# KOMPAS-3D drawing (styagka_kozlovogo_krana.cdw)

Referenced files: стяжка козлового крана.cdw
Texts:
  СДМ1-12.00.000 СБ
  Стяжка козлового крана сборочный чертеж
  Zver
  Microsoft
  Текст на чертеже
  Размерные надписи
  Шероховатость
  Линия-выноска #1
  Линия-выноска #2
  Линия-выноска #3
  Отклонения формы и база
  Заголовок таблицы
  Ячейка таблицы
  Стрелка вида
  Обозначение изменения
  Фигурная скобка
  Номер узла
  Марка координационной оси
  VRCB
  Выносная надпись
  Обозначение узла
  Марка/позиционное обозначение с линией-выноской
  Марка/позиционное обозначение на линии
  Марка/позиционное обозначение без линии-выноски
  Ошибки
  Ошибки размерных линий
  ГОСТ 14806-79-Н1-n-3  5
  ГОСТ 14806-80-Т5-Рн3-  6-50Z50
  1. * Размеры для справок.
  2. Сварные швы внахлестку  без скоса кромок, односторонние,
  выполнить дуговой полуавтоматической сваркой в защитных
  газах плавящимся электродом.
  3. Сварные швы таврового соединения без скоса кромок, двухсторонние,
  прерывистые с шахматным расположением, выполнить дуговой ручной
  сваркой в защитных газах неплавящимся металлическим электродом
  по замкнутой линии.
  4. Неуказанные предельные отклонения размеров Н14, h14,  IT 2
  Уголок   40 х 40 х 2,5 ГОСТ 19771-93   Ст2сп ГОСТ 535-88
  Уголок
  ГОСТ
  Ст2сп
  Швеллер   400 х 95 х 8 ГОСТ 8278-83   Ст2кп ГОСТ 11474-76
  Швеллер гнутый
  Швеллер
  Ст2кп
  Кузьмич
  Передня
  Стяжка козлового
  крана
  сборочный чертеж
  СДМ1-12.00.000 СБ-
Dimensions and other numbers on the sheet: 7; 700; 12040; 10; 250; 500; 20; 370; 155; 150; 550; 275; 750; 30; 1; 2; 3; 93; 88; 0,037; 83; 76; 3,518; 422,16; 1:5; 0; 4; 5; 6; 8; 9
